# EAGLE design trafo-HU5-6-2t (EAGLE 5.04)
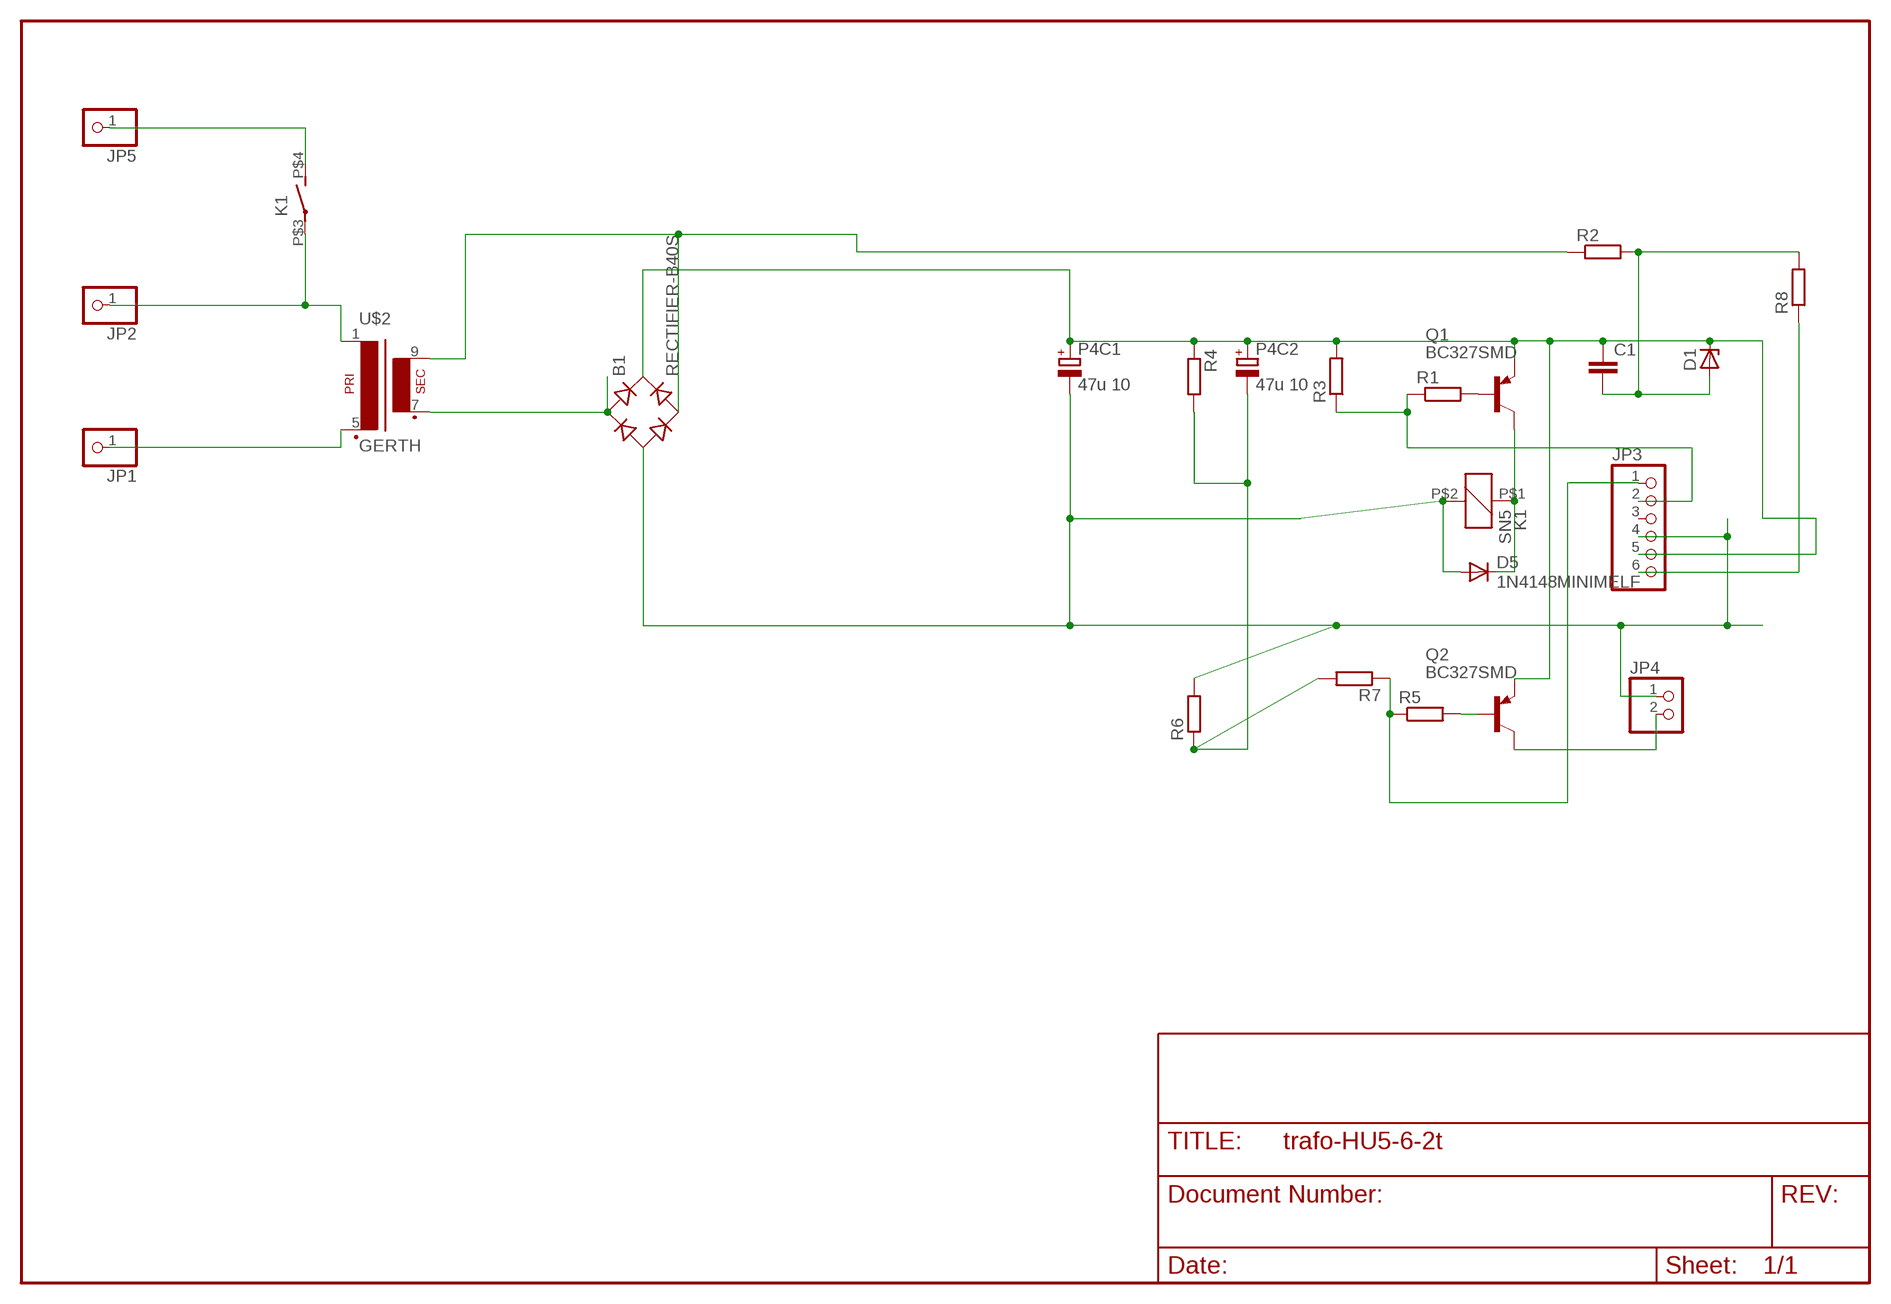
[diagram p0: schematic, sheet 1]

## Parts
B1  RECTIFIER-B40S  [B40S]
C1  C-EUC1206  [C1206]
D1  ZENER-DIODESOT23  [SOT23]
D5  1N4148MINIMELF  [MINIMELF]
JP1  PINHD-1X1  [1X01]
JP2  PINHD-1X1  [1X01]
JP3  PINHD-1X6  [1X06]
JP4  PINHD-1X2  [1X02]
JP5  PINHD-1X1  [1X01]
K1  SN5  [HU]
P4C1  47u 10  CPOL-EUE2-5  [E2-5]
P4C2  47u 10  CPOL-EUE2-5  [E2-5]
Q1  BC327SMD  [SOT23-BEC]
Q2  BC327SMD  [SOT23-BEC]
R1  R-EU_R0805  [R0805]
R2  R-EU_R0805  [R0805]
R3  R-EU_R0805  [R0805]
R4  R-EU_R0805  [R0805]
R5  R-EU_R1206  [R1206]
R6  R-EU_R0805  [R0805]
R7  R-EU_R0805  [R0805]
R8  R-EU_R1206  [R1206]
U$2  GERTH  [150.06]

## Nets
N$1: JP2.1 K1.P$3(2:P) U$2.1
N$2: B1.+ C1.1 D1.3(C) JP3.5 P4C1.+ P4C2.+ Q1.E Q2.E R3.2 R4.1
N$3: B1.- D5.A JP3.4 JP4.1 K1.P$2 P4C1.- R6.2
N$4: JP5.1 K1.P$4(2:S)
N$5: JP1.1 U$2.5(P2)
N$6: B1.AC1 U$2.7(S3)
N$7: B1.AC2 R2.1 U$2.9(S4)
N$8: Q1.B R1.2
N$9: C1.2 D1.1(A) R2.2 R8.2
N$10: JP3.2 R1.1 R3.1
N$11: D5.C K1.P$1 Q1.C
N$12: JP4.2 Q2.C
N$13: JP3.1 R5.1 R7.1
N$14: JP3.6 R8.1
N$15: Q2.B R5.2
N$16: P4C2.- R4.2 R6.1 R7.2
Unconnected: JP3.3

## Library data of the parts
B1 = rectifier:RECTIFIER-: Rectifier
C1 = rcl-2:C-EU: CAPACITOR, European symbol
D1 = diode-1:ZENER-DIODE: Z-Diode
D5 = diode-1:1N4148: DIODE
JP1 JP2 JP5 = pinhead(2):PINHD-1X1: PIN HEADER
JP3 = pinhead:PINHD-1X6: PIN HEADER
JP4 = pinhead:PINHD-1X2: PIN HEADER
K1 = relay:SN*: Slim PCB Relay 1 pole 6 A SCHRACK Source: http://www.schrack.com/.. 5815.pdf
P4C1 P4C2 = rcl:CPOL-EU: POLARIZED CAPACITOR, European symbol
Q1 Q2 = transistor-pnp:BC327*: PNP Transistror
R1-R8 = rcl-2:R-EU_: RESISTOR, European symbol
U$2 = trafo:GERTH

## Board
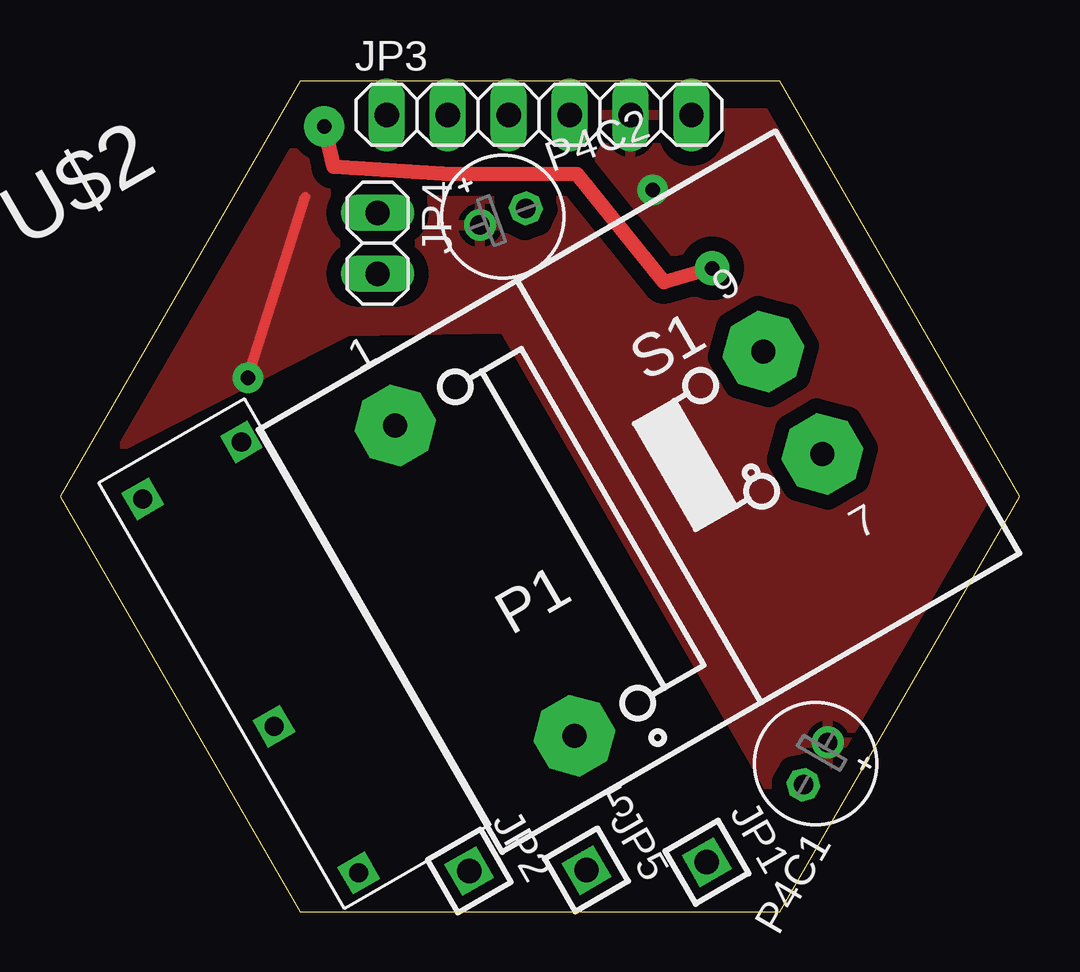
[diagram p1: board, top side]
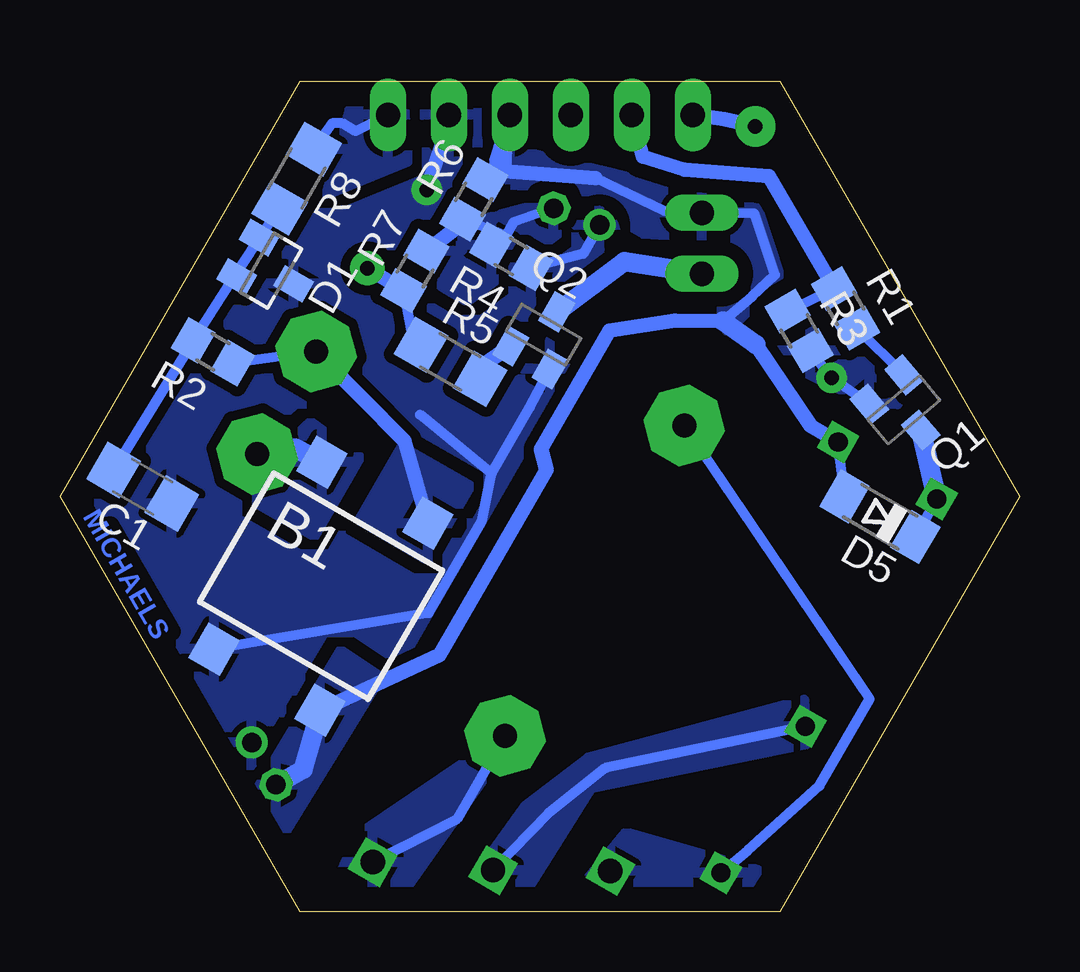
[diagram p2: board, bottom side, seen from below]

Size 40 x 34.64 mm. Coordinates in mm from the lower left corner, seen from the top.
Outline: 10,0 30,0 40,17.32 30,34.64 10,34.64 0,17.32 10,0
Copper layers (1*16): Top 0.035mm / dielectric 1.5mm / Bottom 0.035mm
Design rules "default": minimum track width 10mil, minimum drill 24mil, track to track 8mil, track to pad 8mil, pad to pad 8mil, via to via 8mil, smd to smd 8mil, copper to edge 40mil, drill to drill 8mil, minimum pad ring 10mil, minimum via ring 8mil, stop-mask expansion 4mil, vias tented up to drill 0mil, thermal gap 10mil

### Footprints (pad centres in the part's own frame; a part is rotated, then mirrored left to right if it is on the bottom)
B40S = smd 1.5 x 1.7: + -2.55,-4.5; - 2.55,-4.5; AC1 -2.55,4.5; AC2 2.55,4.5
C1206 = smd 1.6 x 1.8: 1 -1.4,0; 2 1.4,0
SOT23 = smd 1 x 1.4: 1 -0.95,-1.1; 2 0.95,-1.1; 3 0,1.1
MINIMELF = smd 1.4 x 1.8: A 1.7,0; C -1.7,0
1X01 = drill 1.016 square: 1 0,0
1X06 = drill 1.016 long: 1 -6.35,0; 2 -3.81,0; 3 -1.27,0; 4 1.27,0; 5 3.81,0; 6 6.35,0
1X02 = drill 1.016 long: 1 -1.27,0; 2 1.27,0
HU = drill 0.8 square: P$1 2.25,-9; P$2 -2.5,-9; P$3 2.25,9; P$4 2.25,1.95
E2-5 = drill 0.813 pad 1.27 round: + -1.016,0 | drill 0.813 pad 1.27 octagon: - 1.016,0
SOT23-BEC = smd 1 x 1.4: B -0.95,-1.1; C 0,1.1; E 0.95,-1.1
R0805 = smd 1.3 x 1.5: 1 -0.95,0; 2 0.95,0
R1206 = smd 1.6 x 1.803: 1 -1.422,0; 2 1.422,0
150.06 = drill 1 pad 3.175 octagon: 1 -7.417,7.468; 5 -7.417,-7.468; 7 7.417,-2.464; 9 7.417,2.464

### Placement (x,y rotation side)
B1  29.12,13.58 330 bottom
C1  36.55,17.72 150 bottom
D1  31.21,26.74 240 bottom
D5  5.82,16.48 150 bottom
JP1  26.96,2.07 300 top
JP2  17.06,1.7 300 top
JP3  19.97,33.23 0 top
JP4  13.24,27.87 270 top
JP5  21.95,1.74 300 top
K1  9.9,10.55 210 top
P4C1  31.5,6.18 240 top
P4C2  18.46,28.99 20 top
Q1  4.83,20.93 220 bottom
Q2  19.84,24.06 330 bottom
R1  7.25,25.16 300 bottom
R2  33.62,23.35 150 bottom
R3  9.19,24.22 300 bottom
R4  21.18,27.33 150 bottom
R5  23.72,22.93 330 bottom
R6  22.75,29.7 60 bottom
R7  25.2,26.72 60 bottom
R8  30.13,30.57 240 bottom
U$2  24.13,17.52 30 top

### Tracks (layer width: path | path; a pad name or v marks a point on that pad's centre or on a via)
N$1
  Bottom 0.406: U$2.1 6.25,8.87 8.34,5.25 11.32,2.57 K1.P$3
  pour Bottom (isolate 0.61, rank 2): 10.88,1.73 16.42,3.32 18.38,0.93 16.28,-1.02 12.26,-0.41
N$2  (via drill 0.6 pad 1.27)
  Top 0.406: v7.83,22.26 10.22,29.8
  Bottom 0.406: Q1.E v7.83,22.26 R3.2 | Q2.E 20.42,21.02 22.01,18.27 | 22.01,18.27 24.99,20.73 | B1.+ 24.64,12.46 22.41,16.31 22.01,18.27 | P4C2.+ 18.09,27.6 18.19,27.43 R4.1
  Bottom 0.61: v24.71,30.1 23.68,33.17
  pour Top (isolate 0.61, rank 3): 8.87,33.42 1.21,18.73 11.98,24.21 18.52,24.32 31.22,2.33 39.42,17.33 30.21,33.27
  pour Bottom (isolate 0.406, rank 3): 8.87,33.42 1.21,18.73 16.7,26.2 30.67,2.01 39.42,17.33 30.21,33.27
N$3
  Bottom 0.406: D5.A K1.P$2 | 21.79,31.35 R6.2 | 21.39,33.31 JP3.4 | 12.37,24.62 11.15,25.64 10.19,26.55 11.06,29.11 JP4.1 14.81,29.22 17.69,30.59
  Bottom 0.61: B1.- 24.17,10.72 19.73,18.42 19.96,19.29 17.1,24.24 14.36,24.66 12.37,24.62 | K1.P$2 8.69,20.26 10.99,23.64 | JP3.4 21.79,31.35 | 17.69,30.59 21.48,30.87 21.39,33.31
  Bottom 0.813: B1.- 29.86,5.94 P4C1.- | 10.99,23.64 12.37,24.62
  pour Bottom (isolate 0.305): 28.31,10.91 31.91,4.93 31.22,2.33 26.62,9.79
  pour Bottom (isolate 0.61): 21.48,31.9 17.1,30.84 12.51,29.65 10.93,29.33 9.97,26.43 12.15,24.17 13.4,28.11 15.66,28.25 18.96,30.15 21.23,30.29
N$4
  Bottom 0.406: K1.P$4 17.26,6 19.61,4.13 JP5.1
  pour Bottom (isolate 0.61): 20.62,4.42 23.6,0.28 21.37,-0.43 17.85,5.16 8.86,7.01 8.98,8.84 18,6.43
N$5
  Bottom 0.406: U$2.5 23.45,3.87 JP1.1
  pour Bottom (isolate 0.61, rank 2): 27.64,3.19 28.5,1.2 25.49,1.07 20.64,7.95
N$6
  Bottom 0.813: B1.AC1 30.2,19.33 U$2.7
  pour Bottom: 29.56,20.43 32.69,17.55 29.39,15.64 27.49,18.94
N$7
  Bottom 0.406: U$2.9 R2.1
  Bottom 0.61: U$2.9 25.63,19.63 B1.AC2
  pour Bottom: 25.75,19.41 27.53,16.33 24.67,14.68 22.89,17.76
N$8
  Bottom 0.406: Q1.B R1.2
N$9
  Bottom 0.406: R8.2 D1.1 32.44,26.93 R2.2 C1.2
N$10
  Bottom 0.406: 7.67,25.83 R1.1 R3.1 | 16.23,33.12 JP3.2
  Bottom 0.61: 16.23,33.12 15.7,31.49 13.97,30.93 10.46,30.67 R1.1
N$11
  Bottom 0.406: K1.P$1 D5.C
  Bottom 0.813: K1.P$1 Q1.C
N$12
  Bottom 0.813: Q2.C 16.47,27.1 JP4.2
N$13  (via drill 0.6 pad 1.42, 0.6 pad 1.68)
  Top 0.61: v27.19,26.83 25.17,26.26 21.54,30.76 15.97,30.77 11.4,31.06 v11.01,32.75
  Bottom 0.406: R5.1 25.14,23.01 R7.1
  Bottom 0.61: JP3.1 12.3,33.05 v11.01,32.75 | v27.19,26.83 R7.1
N$14
  Bottom 0.406: JP3.6 27.7,32.55 28.25,32.87 28.66,32.87 R8.1
  pour Bottom (isolate 0.305): 25.64,33.57 27.93,33.42 28.9,29.89 25.5,31.28
N$15
  Bottom 0.406: R5.2 22.3,22.84
  Bottom 0.61: 22.3,22.84 Q2.B
N$16
  Bottom 0.406: R6.1 21.41,28.2 21.1,28.75 P4C2.-
  Bottom 0.61: R6.1 23.38,28.6 R7.2
  pour Bottom (isolate 0.406): 19.91,29.53 22.51,28.83 24.02,27.5 24.1,26.08 23,25.45 19.13,28.34

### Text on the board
Bottom: MICHAELS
